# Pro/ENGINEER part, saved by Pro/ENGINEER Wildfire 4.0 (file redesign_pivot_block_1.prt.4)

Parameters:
  METRIC = "NO"

Other parameters: PITCH, DRILL_POINT_ANGLE, DRILL_DEPTH, DRILL_DIAMETER, THREAD_DIAMETER, THREADS_PER_INCH, THREAD_DEPTH, THREAD_LENGTH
